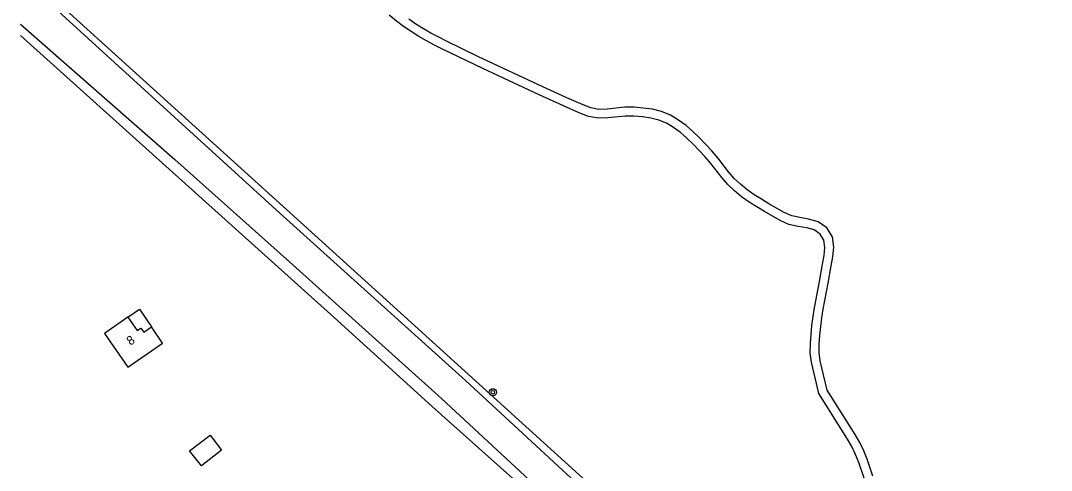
# Model space of a CAD drawing. Extents: x 128999 to 131010, y 395498 to 399007.
# Drawn here: x 129000 to 129116, y 395689.7 to 395740.4 of the extents above; entities that cross this region are included whole.
import ezdxf

# ---------------------------------------------------------------- set-up
doc = ezdxf.new("R2010")
doc.units = 0
for name, color, linetype in [('gg-afsc-draadraster', 7, 'Continuous'), ('gg-afsc-hekwerk', 7, 'Continuous'), ('gg-anno-huisnummerreeks BGT', 7, 'Continuous'), ('gg-bbg-hoofdgebouw', 7, 'Continuous'), ('gg-bbg-luifel en loopbrug', 7, 'Continuous'), ('gg-bbg-overig bouwwerk', 7, 'Continuous'), ('gg-knt-onverhard', 7, 'Continuous'), ('gt-symb-boom', 7, 'Continuous')]:
    doc.layers.add(name, color=color, linetype=linetype)

# ---------------------------------------------------------------- blocks, each defined once
blk = doc.blocks.new('gt0-BOOM')
at = {"layer": 'gt-symb-boom'}
for radius in [0.4, 0.2]:
    blk.add_circle((0, 0), radius, dxfattribs=at)

msp = doc.modelspace()

# ---------------------------------------------------------------- linework, layer by layer
at = {"layer": 'gg-afsc-draadraster'}
msp.add_lwpolyline([(129000, 395746.24), (129031.49, 395717.65), (129084.54, 395669.53), (129097.25, 395657.45), (129113.93, 395643.35)], dxfattribs=at)
at = {"layer": 'gg-afsc-hekwerk'}
msp.add_lwpolyline([(129000, 395738.67), (129035.29, 395706.94), (129046.29, 395696.91), (129063.05, 395681.93)], dxfattribs=at)
at = {"layer": 'gg-bbg-hoofdgebouw'}
for points in [[(129012.08, 395706.99), (129009.43, 395705.15), (129012.05, 395701.35), (129014.71, 395703.18), (129015.98, 395704.04), (129014.74, 395705.87)], [(129012.08, 395706.99), (129013.13, 395705.47), (129013.53, 395705.74), (129013.85, 395705.27), (129014.74, 395705.87)]]:
    msp.add_lwpolyline(points, dxfattribs=at)
at = {"layer": 'gg-bbg-luifel en loopbrug'}
msp.add_lwpolyline([(129012.08, 395706.99), (129013.36, 395707.87), (129014.74, 395705.87)], dxfattribs=at)
at = {"layer": 'gg-bbg-overig bouwwerk'}
msp.add_lwpolyline([(129019, 395691.93), (129021.32, 395693.67), (129022.62, 395692.01), (129020.34, 395690.23), (129019, 395691.93)], dxfattribs=at)
at = {"layer": 'gg-knt-onverhard'}
for points in [[(129000, 395745.31), (129029.17, 395718.67), (129050.05, 395699.85), (129066.39, 395684.71), (129084.01, 395668.71), (129101.96, 395652.5), (129114.06, 395641.59)], [(129094.94, 395688.74), (129094.3, 395690.62), (129093.94, 395691.53), (129093.53, 395692.4), (129093.03, 395693.23), (129089.81, 395698.38), (129088.98, 395701.89), (129088.85, 395702.94), (129088.86, 395703.99), (129088.93, 395705.01), (129089.03, 395706.02), (129089.17, 395707.03), (129089.33, 395708.03), (129089.88, 395710.98), (129090.21, 395712.95), (129090.41, 395713.92), (129090.5, 395714.82), (129090.37, 395715.65), (129089.97, 395716.33), (129089.3, 395716.79), (129088.44, 395717.04), (129087.47, 395717.19), (129086.43, 395717.42), (129085.45, 395717.87), (129083.69, 395718.87), (129082.82, 395719.39), (129081.96, 395719.93), (129081.12, 395720.53), (129080.31, 395721.18), (129079.56, 395721.91), (129078.89, 395722.69), (129077.65, 395724.27), (129077.03, 395725.02), (129075.66, 395726.45), (129074.96, 395727.13), (129074.24, 395727.77), (129073.47, 395728.34), (129072.67, 395728.82), (129071.81, 395729.17), (129070.9, 395729.39), (129069.95, 395729.52), (129068.98, 395729.61), (129068.03, 395729.62), (129066.06, 395729.4), (129064.99, 395729.37), (129063.9, 395729.56), (129062.92, 395729.95), (129061.07, 395730.75), (129058.33, 395732), (129051.99, 395734.97), (129047.47, 395737.13), (129046.57, 395737.59), (129045.68, 395738.08), (129044.8, 395738.58), (129043.94, 395739.12), (129043.09, 395739.7), (129042.28, 395740.31), (129041.48, 395740.96)], [(129095.88, 395689.07), (129095.23, 395690.97), (129094.86, 395691.93), (129094.41, 395692.87), (129093.89, 395693.75), (129090.74, 395698.77), (129089.97, 395702.07), (129089.85, 395703), (129089.86, 395703.95), (129089.93, 395704.92), (129090.03, 395705.91), (129090.16, 395706.88), (129090.31, 395707.86), (129090.87, 395710.8), (129091.2, 395712.77), (129091.4, 395713.77), (129091.51, 395714.85), (129091.33, 395716), (129090.71, 395717.03), (129089.73, 395717.71), (129088.66, 395718.01), (129087.66, 395718.18), (129086.75, 395718.37), (129085.91, 395718.76), (129084.19, 395719.74), (129083.34, 395720.24), (129082.52, 395720.76), (129081.72, 395721.33), (129080.98, 395721.93), (129080.29, 395722.6), (129079.66, 395723.33), (129078.43, 395724.9), (129077.78, 395725.69), (129076.37, 395727.15), (129075.64, 395727.86), (129074.87, 395728.55), (129074.03, 395729.17), (129073.12, 395729.71), (129072.12, 395730.13), (129071.09, 395730.38), (129070.06, 395730.51), (129069.04, 395730.61), (129067.99, 395730.62), (129065.98, 395730.4), (129065.06, 395730.37), (129064.17, 395730.53), (129063.3, 395730.88), (129061.47, 395731.66), (129058.75, 395732.91), (129051.51, 395736.3), (129047.92, 395738.03), (129047.04, 395738.48), (129046.17, 395738.95), (129045.32, 395739.44), (129044.48, 395739.96), (129043.67, 395740.51)], [(129000, 395739.97), (129017.34, 395724.73), (129030.24, 395713.19), (129047.37, 395697.8), (129064.02, 395682.34), (129081.97, 395666.22), (129099.27, 395649.94), (129123.64, 395628.08), (129146.6, 395607.66), (129169.7, 395587.28), (129199.22, 395559.73), (129231.57, 395530.15), (129252.63, 395511.74), (129266.59, 395500)]]:
    msp.add_lwpolyline(points, dxfattribs=at)

# ---------------------------------------------------------------- block references
at = {"layer": 'gt-symb-boom'}
msp.add_blockref('gt0-BOOM', (129053.13, 395698.52), dxfattribs=at)

# ---------------------------------------------------------------- texts
at = {"layer": 'gg-anno-huisnummerreeks BGT'}
msp.add_text('8', height=1, rotation=34.6, dxfattribs=at).set_placement((129012.35, 395703.75))

doc.saveas('drawing.dxf')
